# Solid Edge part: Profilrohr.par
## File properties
Username: bmolnar
Dokumentum tartalom típus: 0
Author: bmolnar
Last saved by: bmolnar
Revision: 80
Sűrűség: 0,000 kg/m^3
Pontosság: 0,990
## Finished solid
Body 1: solid body, 59 faces, 170 edges, 112 vertices.
  Faces by surface: plane 30, cylinder 29
  Edges by curve: line 112, circle 58
Bounding box of the edges (mm): 40.000 x 39.000 x 40.000, from (-20, -9.5, -20) to (20, 29.5, 20).
Cylindrical faces by radius (mm): R0.2 x12, R0.5 x12, R5 x4, R12.5 x1
Planar faces by outward normal: +x 7, +y 1, +z 7, -x 7, -y 1, -z 7
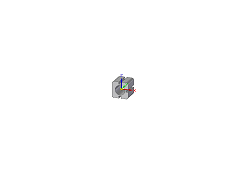
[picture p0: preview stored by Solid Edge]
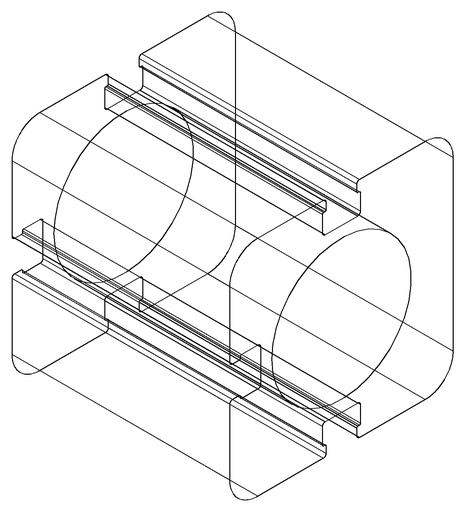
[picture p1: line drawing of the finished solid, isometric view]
